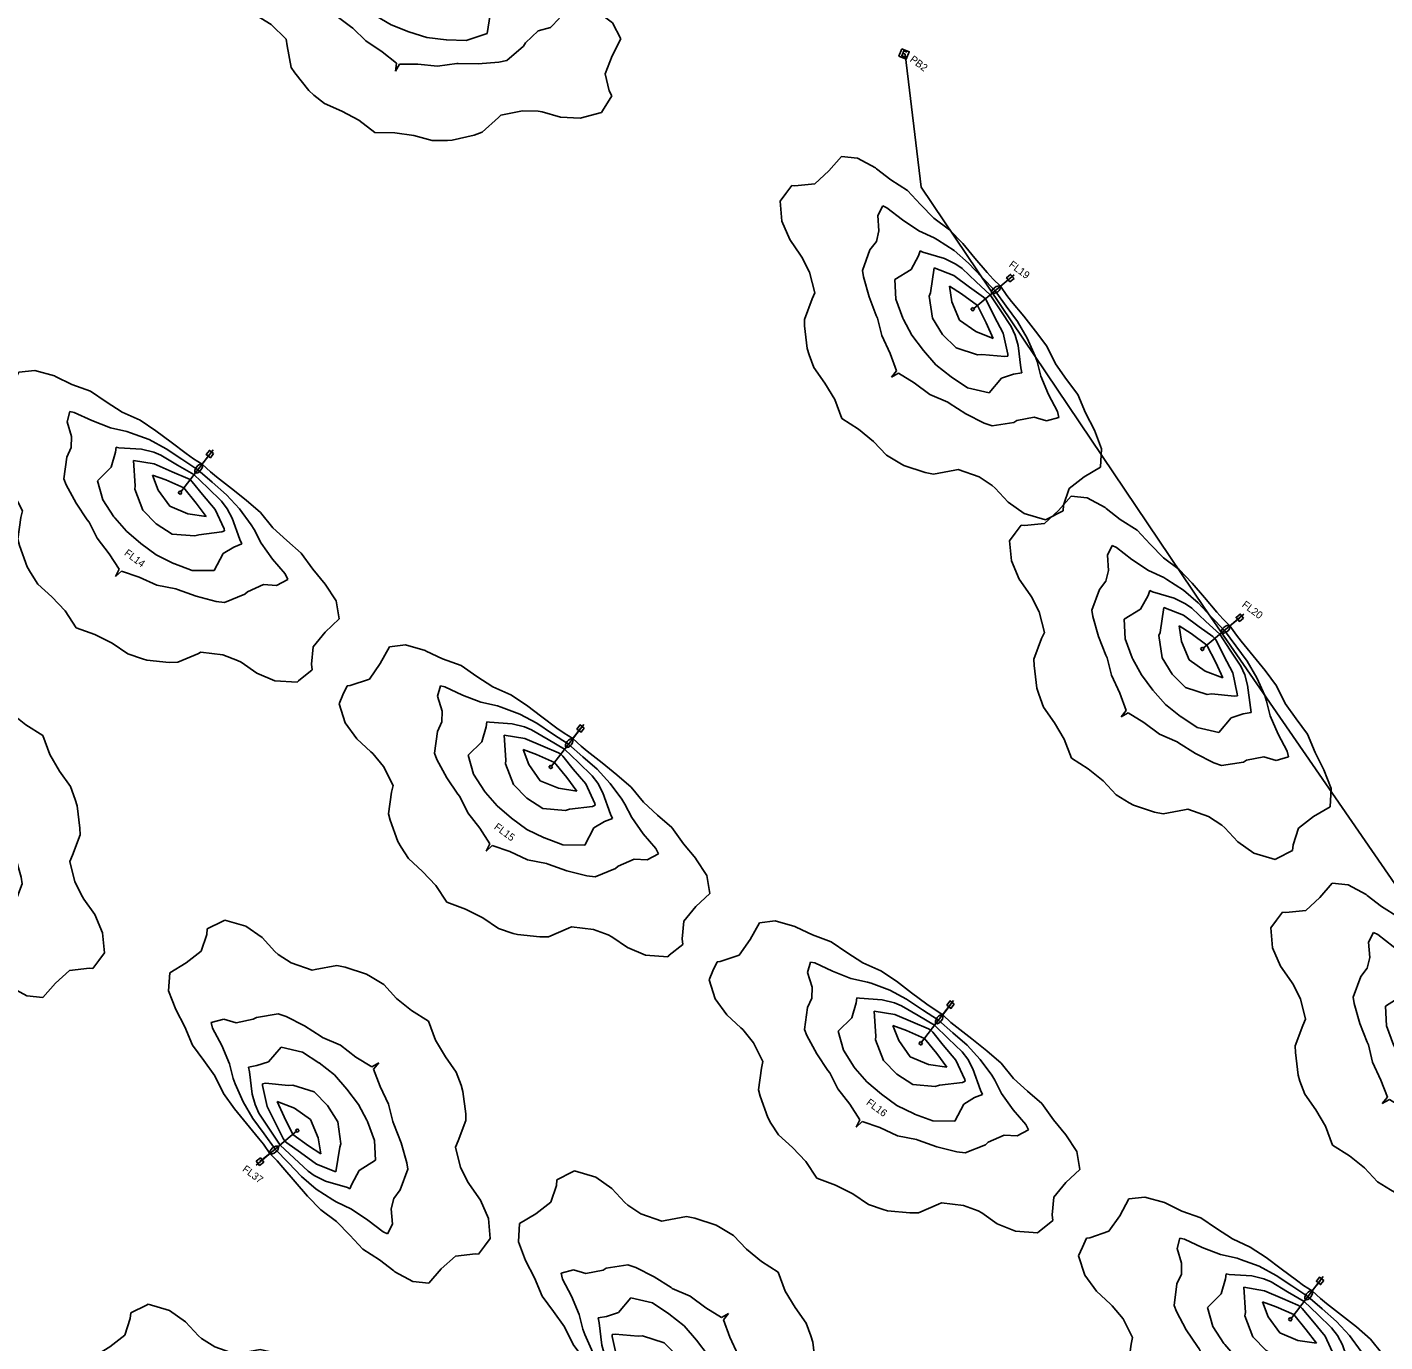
# Model space of a CAD drawing. Extents: x 1322666 to 1327584, y 458075 to 462260.
# Drawn here: x 1325072 to 1325587, y 459866 to 460364 of the extents above; entities that cross this region are included whole.
import ezdxf

# ---------------------------------------------------------------- set-up
doc = ezdxf.new("R2010")
doc.units = 0
for name, color, linetype in [('Default', 7, 'Continuous'), ('DR_P_Culvert', 7, 'Continuous'), ('DR_X_Cells', 7, 'Continuous'), ('PF_X_Ground_Line', 7, 'Continuous'), ('UT_X_Misc_Cells', 7, 'Continuous')]:
    doc.layers.add(name, color=color, linetype=linetype)

# ---------------------------------------------------------------- blocks, each defined once
blk = doc.blocks.new('AGI32-IDj66arb-Project_1-LUMINAIRE-ERL2_19C330______Symbol')
at = {"layer": 'Default'}
for p, q in [((-0.03, 0), (0.03, 0)), ((0, 0.13), (0.24, 0.13)), ((0, -0.13), (0, 0.13)), ((0, 0.13), (0, 0.13)), ((0, 0.13), (0.24, 0.13)), ((0.24, 0.13), (0, 0.13)), ((0, -0.13), (0, 0.13)), ((0, 0.13), (0, 0.13)), ((0, 0.13), (0, -0.13)), ((0.24, 0.13), (0, 0.13)), ((0, 0.13), (0, -0.13)), ((0, -0.03), (0, 0.03)), ((0, 0.03), (0.03, 0)), ((0, -0.03), (0.03, 0)), ((0.24, 0.13), (0.24, -0.13)), ((0.24, 0.13), (0.24, 0.13)), ((0.24, 0.13), (0.24, 0.13)), ((0.24, 0.13), (0.24, -0.13)), ((0.24, -0.13), (0.24, 0.13)), ((0.24, -0.13), (0.24, 0.13)), ((0.24, -0.13), (0, -0.13)), ((0.24, -0.13), (0, -0.13)), ((0, -0.13), (0, -0.13)), ((0, -0.13), (0.24, -0.13)), ((0, -0.13), (0, -0.13)), ((0, -0.13), (0.24, -0.13)), ((0.24, -0.13), (0.24, -0.13)), ((0.24, -0.13), (0.24, -0.13))]:
    blk.add_line(p, q, dxfattribs=at)
blk = doc.blocks.new('AGI32-IDj66arb-Project_1-LUMINAIRE-ERL2_19C330______64-1')
at = {"layer": 'Default'}
blk.add_blockref('AGI32-IDj66arb-Project_1-LUMINAIRE-ERL2_19C330______Symbol', (0, 0), dxfattribs=at)
blk = doc.blocks.new('AGI32-IDj66arb-Project_1-LUMINAIRE-ERL2_19C330______Template1')
at = {"layer": 'Default'}
for p, q in [((9.14, 19.22), (10.58, 20.11)), ((10.58, 20.11), (10.97, 20.5)), ((10.97, 20.5), (12.6, 20.11)), ((12.6, 20.11), (12.8, 20.07)), ((12.8, 20.07), (13.99, 18.29)), ((4.29, 18.29), (5.49, 19.56)), ((5.49, 19.56), (7.31, 19.28)), ((7.31, 19.28), (9.14, 19.22)), ((3.66, 16.46), (4.29, 18.29)), ((13.99, 18.29), (14.48, 16.46)), ((3.25, 14.63), (3.66, 16.45)), ((3.66, 16.45), (3.66, 16.46)), ((14.48, 16.46), (14.57, 14.63)), ((2.69, 12.8), (3.25, 14.63)), ((14.57, 14.63), (14.63, 14.24)), ((5.23, 12.8), (5.49, 13.32)), ((5.49, 13.32), (6.62, 12.8)), ((14.63, 14.24), (15.08, 12.8)), ((2.59, 10.97), (2.69, 12.8)), ((4.85, 10.97), (5.23, 12.8)), ((6.62, 12.8), (7.31, 11.77)), ((15.08, 12.8), (16.17, 10.97)), ((2.44, 9.14), (2.59, 10.97)), ((4.29, 9.14), (4.85, 10.97)), ((7.31, 11.77), (8.8, 10.97)), ((8.8, 10.97), (9.14, 10.91)), ((9.14, 10.91), (10.97, 9.83)), ((16.17, 10.97), (16.46, 10.82)), ((16.46, 10.82), (18.29, 9.79)), ((10.97, 9.83), (11.39, 9.14)), ((18.29, 9.79), (18.8, 9.14)), ((2, 7.31), (2.44, 9.14)), ((3.66, 7.83), (4.29, 9.14)), ((11.39, 9.14), (12.17, 7.31)), ((18.8, 9.14), (19.94, 7.31)), ((1.89, 5.49), (2, 7.31)), ((2.95, 5.49), (3.47, 7.31)), ((3.47, 7.31), (3.66, 7.83)), ((4.09, 5.49), (5.27, 7.31)), ((5.27, 7.31), (5.49, 7.72)), ((5.49, 7.72), (6.19, 7.31)), ((6.19, 7.31), (7.31, 6.87)), ((7.31, 6.87), (9.14, 7.19)), ((9.14, 7.19), (10.42, 5.49)), ((12.17, 7.31), (12.76, 5.49)), ((19.94, 7.31), (20.11, 6.9)), ((20.11, 6.9), (20.59, 5.49)), ((1.86, 3.66), (1.89, 5.49)), ((2.64, 3.66), (2.95, 5.49)), ((3.66, 4.54), (4.09, 5.49)), ((4.43, 3.66), (5.39, 5.49)), ((5.39, 5.49), (5.49, 5.63)), ((5.49, 5.63), (5.75, 5.49)), ((5.75, 5.49), (7.31, 3.9)), ((10.42, 5.49), (10.97, 3.69)), ((12.76, 5.49), (12.8, 5.34)), ((12.8, 5.34), (13.64, 3.66)), ((20.59, 5.49), (20.69, 3.66)), ((3.42, 3.66), (3.66, 4.54)), ((1.85, 1.83), (1.86, 3.66)), ((2.53, 1.83), (2.64, 3.66)), ((3.22, 1.83), (3.42, 3.66)), ((4.03, 1.83), (4.43, 3.66)), ((5.05, 1.83), (5.49, 3.41)), ((5.49, 3.41), (6.36, 1.83)), ((7.31, 3.9), (7.65, 3.66)), ((7.65, 3.66), (8.83, 1.83)), ((10.97, 3.69), (10.98, 3.66)), ((10.98, 3.66), (11.36, 1.83)), ((13.64, 3.66), (14.06, 1.83)), ((20.69, 3.66), (21.05, 1.83)), ((1.83, 1.08), (1.85, 1.83)), ((2.41, 0), (2.53, 1.83)), ((3.01, 0), (3.22, 1.83)), ((3.66, 0.28), (4.03, 1.83)), ((4.62, 0), (5.05, 1.83)), ((6.36, 1.83), (6.85, 0)), ((8.83, 1.83), (8.98, 0)), ((11.36, 1.83), (11.4, 0)), ((14.06, 1.83), (14.63, 0.14)), ((21.05, 1.83), (21.63, 0)), ((1.73, 0), (1.83, 1.08)), ((3.62, 0), (3.66, 0.28)), ((14.63, 0.14), (15.4, 0)), ((1.83, -0.98), (1.73, 0)), ((1.85, -1.83), (1.83, -0.98)), ((2.55, -1.83), (2.41, 0)), ((3.25, -1.83), (3.01, 0)), ((3.66, -0.25), (3.62, 0)), ((4.07, -1.83), (3.66, -0.25)), ((5.07, -1.83), (4.62, 0)), ((6.85, 0), (6.29, -1.83)), ((8.98, 0), (8.72, -1.83)), ((11.4, 0), (11.31, -1.83)), ((14.63, -0.15), (14.04, -1.83)), ((15.4, 0), (14.63, -0.15)), ((21.63, 0), (20.99, -1.83)), ((1.88, -3.66), (1.85, -1.83)), ((2.67, -3.66), (2.55, -1.83)), ((3.47, -3.66), (3.25, -1.83)), ((4.53, -3.66), (4.07, -1.83)), ((5.49, -3.15), (5.07, -1.83)), ((6.29, -1.83), (5.49, -3.15)), ((8.72, -1.83), (7.6, -3.66)), ((11.31, -1.83), (10.97, -3.51)), ((14.04, -1.83), (13.56, -3.66)), ((20.99, -1.83), (20.7, -3.66)), ((1.89, -5.49), (1.88, -3.66)), ((2.97, -5.49), (2.67, -3.66)), ((3.66, -4.38), (3.47, -3.66)), ((5.49, -5.44), (4.53, -3.66)), ((7.31, -3.83), (5.49, -5.44)), ((7.6, -3.66), (7.31, -3.83)), ((10.94, -3.66), (10.29, -5.49)), ((10.97, -3.51), (10.94, -3.66)), ((13.56, -3.66), (12.8, -5.21)), ((20.7, -3.66), (20.55, -5.49)), ((4.15, -5.49), (3.66, -4.38)), ((12.8, -5.21), (12.73, -5.49)), ((2.03, -7.31), (1.89, -5.49)), ((3.54, -7.31), (2.97, -5.49)), ((5.37, -7.31), (4.15, -5.49)), ((10.29, -5.49), (9.14, -7.01)), ((12.73, -5.49), (12.12, -7.31)), ((20.55, -5.49), (20.11, -6.73)), ((2.46, -9.14), (2.03, -7.31)), ((3.66, -7.66), (3.54, -7.31)), ((4.35, -9.14), (3.66, -7.66)), ((5.49, -7.55), (5.37, -7.31)), ((5.91, -7.31), (5.49, -7.55)), ((7.31, -6.76), (5.91, -7.31)), ((9.14, -7.01), (7.31, -6.76)), ((12.12, -7.31), (11.3, -9.14)), ((19.86, -7.31), (18.68, -9.14)), ((20.11, -6.73), (19.86, -7.31)), ((2.61, -10.97), (2.46, -9.14)), ((4.89, -10.97), (4.35, -9.14)), ((11.3, -9.14), (10.97, -9.68)), ((18.68, -9.14), (18.29, -9.64)), ((10.97, -9.68), (9.14, -10.74)), ((18.29, -9.64), (16.46, -10.68)), ((2.71, -12.8), (2.61, -10.97)), ((5.29, -12.8), (4.89, -10.97)), ((7.31, -11.59), (6.44, -12.8)), ((8.15, -10.97), (7.31, -11.59)), ((9.14, -10.74), (8.15, -10.97)), ((15.87, -10.97), (14.99, -12.8)), ((16.46, -10.68), (15.87, -10.97)), ((3.3, -14.63), (2.71, -12.8)), ((5.49, -13.2), (5.29, -12.8)), ((6.44, -12.8), (5.49, -13.2)), ((14.99, -12.8), (14.63, -14.39)), ((14.63, -14.39), (14.6, -14.63)), ((3.66, -16.33), (3.3, -14.63)), ((14.6, -14.63), (14.44, -16.46)), ((3.68, -16.46), (3.66, -16.33)), ((4.41, -18.29), (3.68, -16.46)), ((14.44, -16.46), (13.9, -18.29)), ((5.49, -19.4), (4.41, -18.29)), ((13.9, -18.29), (12.8, -19.89)), ((7.31, -19.11), (5.49, -19.4)), ((9.14, -19.03), (7.31, -19.11)), ((10.75, -20.11), (9.14, -19.03)), ((10.97, -20.33), (10.75, -20.11)), ((11.9, -20.11), (10.97, -20.33)), ((12.8, -19.89), (11.9, -20.11))]:
    blk.add_line(p, q, dxfattribs=at)
blk = doc.blocks.new('AGI32-IDj66arb-Project_1-LUMINAIRE-ERL2_19C330______64')
at = {"layer": 'Default'}
for q in [(5.08, 0), (0, 0)]:
    blk.add_line((0, 0), q, dxfattribs=at)
for name, p in [('AGI32-IDj66arb-Project_1-LUMINAIRE-ERL2_19C330______Template1', (0, 0)), ('AGI32-IDj66arb-Project_1-LUMINAIRE-ERL2_19C330______64-1', (5.08, 0))]:
    blk.add_blockref(name, p, dxfattribs=at)

msp = doc.modelspace()

# ---------------------------------------------------------------- linework, layer by layer
at = {"layer": 'DR_P_Culvert'}
for p, q in [((1325444.72, 460269.2), (1325440.86, 460266.03)), ((1325141.13, 460202.44), (1325138.05, 460198.5)), ((1325531.79, 460140.35), (1325527.92, 460137.18)), ((1325281.73, 460098.3), (1325278.65, 460094.36)), ((1325422.06, 459993.57), (1325418.98, 459989.63)), ((1325160.12, 459934.02), (1325163.98, 459937.2)), ((1325562.23, 459888.81), (1325559.15, 459884.87))]:
    msp.add_line(p, q, dxfattribs=at)
for points in [[(1325446.13, 460269.06), (1325444.58, 460267.79), (1325443.31, 460269.34), (1325444.86, 460270.61)], [(1325142.53, 460202.61), (1325141.3, 460201.03), (1325139.72, 460202.26), (1325140.96, 460203.84)], [(1325533.19, 460140.22), (1325531.65, 460138.95), (1325530.38, 460140.49), (1325531.92, 460141.76)], [(1325283.13, 460098.48), (1325281.9, 460096.9), (1325280.32, 460098.13), (1325281.56, 460099.71)], [(1325423.46, 459993.74), (1325422.23, 459992.17), (1325420.66, 459993.4), (1325421.89, 459994.97)], [(1325158.71, 459934.16), (1325160.25, 459935.43), (1325161.52, 459933.88), (1325159.98, 459932.61)], [(1325563.63, 459888.99), (1325562.4, 459887.41), (1325560.83, 459888.64), (1325562.06, 459890.22)]]:
    msp.add_lwpolyline(points, close=True, dxfattribs=at)
for centre, major_axis in [((1325439.31, 460264.76), (-1.55, -1.27)), ((1325136.82, 460196.92), (-1.23, -1.58)), ((1325526.38, 460135.91), (-1.55, -1.27)), ((1325277.42, 460092.79), (-1.23, -1.58)), ((1325417.75, 459988.05), (-1.23, -1.58)), ((1325165.52, 459938.46), (1.55, 1.27)), ((1325557.92, 459883.3), (-1.23, -1.58))]:
    msp.add_ellipse(centre, major_axis=major_axis, ratio=0.5, dxfattribs=at)
at = {"layer": 'DR_X_Cells'}
msp.add_line((1325403.91, 460354.5), (1325404.84, 460354.12), dxfattribs=at)
msp.add_lwpolyline([(1325403.63, 460356.23), (1325406.41, 460355.09), (1325405.27, 460352.31), (1325402.49, 460353.45)], close=True, dxfattribs=at)
msp.add_lwpolyline([(1325405.45, 460354.95), (1325404.29, 460355.43), (1325403.53, 460353.58), (1325404.69, 460353.1)], dxfattribs=at)
at = {"layer": 'PF_X_Ground_Line'}
msp.add_lwpolyline([(1325404.84, 460354.12), (1325410.9, 460303.73), (1325518.28, 460144.22), (1325611.69, 460008.79), (1325708.15, 459878.81), (1325758.82, 459817.69), (1325849.94, 459728.51), (1325856.7, 459721.64), (1325856.7, 459721.64)], dxfattribs=at)

# ---------------------------------------------------------------- block references
at = {"layer": 'DR_P_Culvert'}
for p, xscale, yscale, rotation in [((1325069.37, 460453.42), 3.9370000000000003, 3.9369999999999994, -108.74000354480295), ((1325231.01, 460405.12), 3.9370000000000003, 3.9369999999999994, -108.74000354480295), ((1325446.22, 460270.5), 3.937000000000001, 3.9370000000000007, -140.18243234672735), ((1325142.31, 460204.03), 3.9370000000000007, 3.9370000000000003, -127.5957929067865), ((1325533.29, 460141.65), 3.937000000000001, 3.9370000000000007, -140.18243234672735), ((1325012.29, 460041.09), 3.937, 3.9370000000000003, 39.81756765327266), ((1325282.91, 460099.9), 3.9370000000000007, 3.9370000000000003, -127.5957929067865), ((1325632.39, 459994.85), 3.937000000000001, 3.9370000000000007, -140.18243234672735), ((1325158.61, 459932.72), 3.937, 3.9370000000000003, 39.81756765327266), ((1325423.24, 459995.17), 3.9370000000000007, 3.9370000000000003, -127.5957929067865), ((1325291.28, 459837.53), 3.937, 3.9370000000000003, 39.81756765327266), ((1325563.41, 459890.41), 3.9370000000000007, 3.9370000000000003, -127.5957929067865), ((1325129.62, 459787), 3.937, 3.9370000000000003, 39.81756765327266)]:
    msp.add_blockref('AGI32-IDj66arb-Project_1-LUMINAIRE-ERL2_19C330______64', p, dxfattribs=dict(at, xscale=xscale, yscale=yscale, rotation=rotation))

# ---------------------------------------------------------------- texts
at = {"layer": 'UT_X_Misc_Cells'}
for s, p in [('PB2', (1325406.38, 460351.62)), ('FL19', (1325443.93, 460273.78)), ('FL14', (1325108.38, 460164.37)), ('FL20', (1325532.34, 460144.78)), ('FL15', (1325248.66, 460060.48)), ('FL16', (1325389.84, 459955.92)), ('FL37', (1325153.18, 459930.64))]:
    msp.add_text(s, height=2.8, rotation=323.4759, dxfattribs=at).set_placement(p)

doc.saveas('drawing.dxf')
